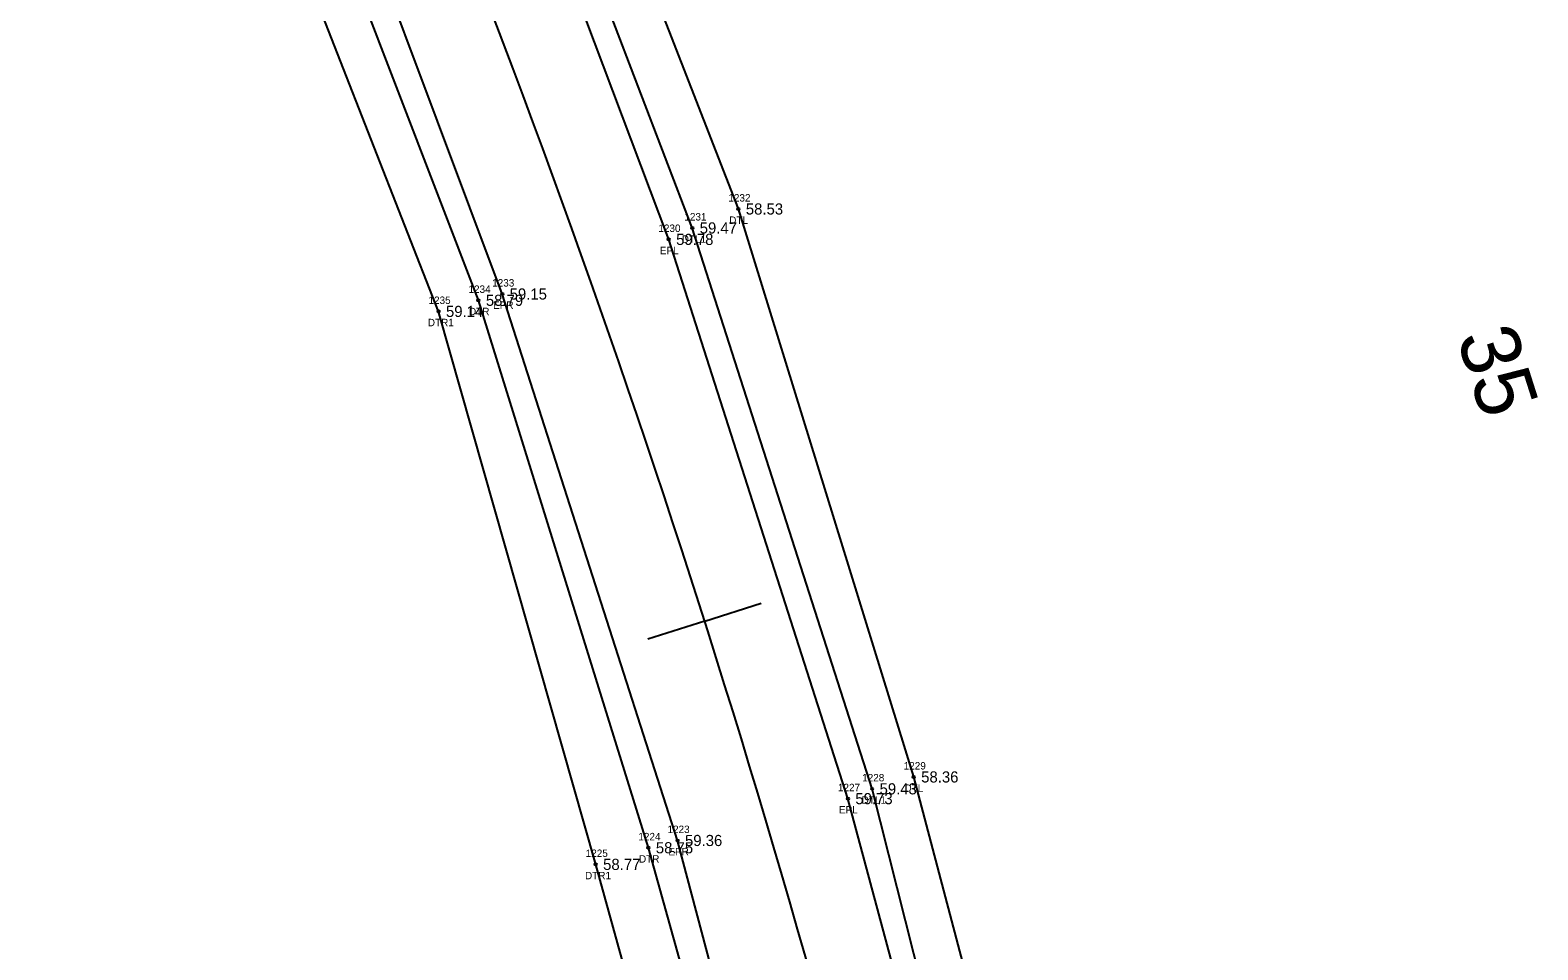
# Model space of a CAD drawing. Extents: x 2396531 to 2397633, y 770203 to 772837.
# Drawn here: x 2397429.9 to 2397632.8, y 770334.5 to 770458.3 of the extents above; entities that cross this region are included whole.
import ezdxf

# ---------------------------------------------------------------- set-up
doc = ezdxf.new("R2010")
doc.units = 0
for name, color, linetype in [('RD_EX_H2O', 7, 'Continuous'), ('RD_EX_H2O_txCode', 7, 'Continuous'), ('RD_EX_Road', 7, 'Continuous'), ('RD_EX_Road_txCode', 7, 'Continuous'), ('RD_EX_TX_H2O_ELEV', 7, 'Continuous'), ('RD_EX_TX_Road_ELEV', 7, 'Continuous'), ('RD_HC_Cl', 7, 'Continuous'), ('RD_HC_Data_Tic', 7, 'Continuous'), ('RD_HC_TX_Sta50', 7, 'Continuous'), ('RD_SMD_Locator', 7, 'Continuous')]:
    doc.layers.add(name, color=color, linetype=linetype)

msp = doc.modelspace()

# ---------------------------------------------------------------- linework, layer by layer
at = {"layer": 'RD_EX_H2O'}
for points in [[(2397586.15, 770211.51), (2397567.31, 770287.61), (2397548.79, 770357.79), (2397525.19, 770434.22), (2397495.53, 770510.39), (2397465.51, 770576.5), (2397430.55, 770645.5), (2397380.29, 770734.7), (2397327.01, 770824.44), (2397291.42, 770882.36)], [(2397579.43, 770209.93), (2397561.1, 770285.3), (2397543.19, 770356.19), (2397518.98, 770431.67), (2397489.88, 770507.8), (2397460.56, 770573.86), (2397425.02, 770642.83), (2397373.6, 770730.3), (2397319.08, 770819.92), (2397284.14, 770878.8)], [(2397544.21, 770204.98), (2397524.44, 770279.37), (2397505.98, 770346.02), (2397484.83, 770420.44), (2397457.62, 770489.91), (2397433.59, 770544.23), (2397438.3, 770546.59)], [(2397549.62, 770204.86), (2397531.98, 770280.53), (2397513.08, 770348.26), (2397490.2, 770421.93), (2397463.3, 770492), (2397438.3, 770546.59)]]:
    msp.add_lwpolyline(points, dxfattribs=at)
at = {"layer": 'RD_EX_Road'}
for points in [[(2397576.88, 770209.21), (2397558.85, 770284.47), (2397539.93, 770354.87), (2397515.81, 770430.13), (2397486.97, 770506.75), (2397457.82, 770572.7), (2397422.37, 770641.75), (2397371.16, 770729.12), (2397316.57, 770818.52), (2397280.76, 770876.73)], [(2397553.19, 770205.48), (2397535.12, 770280.96), (2397517, 770349.24), (2397493.4, 770422.78), (2397467.13, 770492.9), (2397441.16, 770551.74), (2397436.66, 770561.67), (2397402.21, 770629.28), (2397353, 770712.83), (2397296, 770806.32), (2397260.16, 770864.73)]]:
    msp.add_lwpolyline(points, dxfattribs=at)
at = {"layer": 'RD_HC_Cl'}
msp.add_arc((2396086.26, 769922.93), 1505.07, 12.92958, 31.50817, dxfattribs=at)
at = {"layer": 'RD_HC_Data_Tic'}
for q in [(2397528.27, 770381.18), (2397513.02, 770376.34)]:
    msp.add_line((2397520.65, 770378.76), q, dxfattribs=at)
at = {"layer": 'RD_SMD_Locator'}
for centre in [(2397525.19, 770434.22), (2397518.98, 770431.67), (2397515.81, 770430.13), (2397490.2, 770421.93), (2397493.4, 770422.78), (2397484.83, 770420.44), (2397543.19, 770356.19), (2397548.79, 770357.79), (2397539.93, 770354.87), (2397513.08, 770348.26), (2397517, 770349.24), (2397505.98, 770346.02)]:
    msp.add_circle(centre, 0.15, dxfattribs=at)

# ---------------------------------------------------------------- texts
at = {"layer": 'RD_EX_H2O_txCode'}
for s, p in [('1232', (2397523.84, 770435.22)), ('1231', (2397517.92, 770432.67)), ('DTL', (2397523.95, 770432.22)), ('DTL1', (2397517.57, 770429.67)), ('1234', (2397488.86, 770422.93)), ('1235', (2397483.48, 770421.44)), ('DTR1', (2397483.39, 770418.44)), ('DTR', (2397488.93, 770419.93)), ('1229', (2397547.44, 770358.79)), ('1228', (2397541.85, 770357.19)), ('DTL', (2397547.54, 770355.79)), ('DTL1', (2397541.78, 770354.19)), ('1224', (2397511.73, 770349.26)), ('1225', (2397504.64, 770347.02)), ('DTR', (2397511.81, 770346.26)), ('DTR1', (2397504.55, 770344.02))]:
    msp.add_text(s, height=1, dxfattribs=at).set_placement(p)
at = {"layer": 'RD_EX_Road_txCode'}
for s, p in [('1230', (2397514.42, 770431.13)), ('EPL', (2397514.61, 770428.13)), ('1233', (2397492.05, 770423.78)), ('EPR', (2397492.17, 770420.78)), ('1227', (2397538.59, 770355.87)), ('EPL', (2397538.73, 770352.87)), ('1223', (2397515.65, 770350.24)), ('EPR', (2397515.77, 770347.24))]:
    msp.add_text(s, height=1, dxfattribs=at).set_placement(p)
at = {"layer": 'RD_EX_TX_H2O_ELEV'}
for s, p in [('58.53', (2397526.19, 770433.47)), ('59.47', (2397519.98, 770430.92)), ('58.79', (2397491.2, 770421.18)), ('59.14', (2397485.83, 770419.69)), ('58.36', (2397549.79, 770357.04)), ('59.43', (2397544.19, 770355.44)), ('58.75', (2397514.08, 770347.51)), ('58.77', (2397506.98, 770345.27))]:
    msp.add_text(s, height=1.5, dxfattribs=at).set_placement(p)
at = {"layer": 'RD_EX_TX_Road_ELEV'}
for s, p in [('59.78', (2397516.81, 770429.38)), ('59.15', (2397494.4, 770422.03)), ('59.73', (2397540.93, 770354.12)), ('59.36', (2397518, 770348.49))]:
    msp.add_text(s, height=1.5, dxfattribs=at).set_placement(p)
at = {"layer": 'RD_HC_TX_Sta50'}
msp.add_text('35', height=8, rotation=287.6297, dxfattribs=at).set_placement((2397621.83, 770416.96))

doc.saveas('drawing.dxf')
